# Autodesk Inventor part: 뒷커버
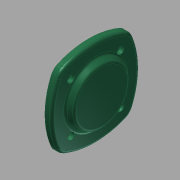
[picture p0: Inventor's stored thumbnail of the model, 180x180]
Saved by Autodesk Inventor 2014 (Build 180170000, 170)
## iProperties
Created: 2015-11
Part Number: 뒷커버
Material: 일반
Document SubType Name: Modeling
Designer: mduedu
Density: 1 g/cm^3
Appearance: 매끄러움 - 짙은 바다 녹색
Mass: 120.056 g
Surface Area: 247.583 cm^2
Volume: 120.056 cm^3
Author: mduedu
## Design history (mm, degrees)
sketch "스케치1"
  geometry: L1 (50, 50)-(-50, 50); L2 (-50, 50)-(-50, -50); L3 (-50, -50)-(50, -50); L4 (50, -50)-(50, 50); L5 (0, 50)-(0, -50); L6 (50, 0)-(-50, 0); A1 r 90 centre (-40, 0) between (40.415, -40.415) and (40.415, 40.415); A2 r 90 centre (40, 0) between (-40.415, 40.415) and (-40.415, -40.415); A3 r 90 centre (0, -40) between (40.415, 40.415) and (-40.415, 40.415); A4 r 90 centre (0, 40) between (-40.415, -40.415) and (40.415, -40.415); 2 further points
  constraints: 12 end point, 8 point on circle, 5 midpoint, 4 centre point, 2 horizontal alignment, 2 parallel, 2 perpendicular, 2 symmetric about line, 2 tangent, 2 vertical alignment, 1 equal radius, 1 horizontal, 2 other
  dimensions: "d0" = 100 distance of L3.end L1.start; "d2" = 90 radius of A1
extrude "돌출1" new body sketch "스케치1" distance "d3" = 8; taper "d4" = 0 deg
sketch "스케치2"
  geometry: C1 r 35 at (0, 0); 1 further point
  constraints: 1 centre point, 1 coincident
  dimensions: "d5" = 70 diameter of C1
extrude "돌출2" join sketch "스케치2" distance "d6" = 7; taper "d7" = -30 deg
sketch "스케치3"
  geometry: L1 (0, 0)-(0, 40); L2 (0, 0)-(-28.284, 28.284); A1 r 40 centre (0, 0) between (0, 40) and (-28.284, 28.284); 2 further points
  constraints: 4 end point, 2 coincident, 2 point on circle, 1 centre point, 1 vertical
  dimensions: "d8" = 80 diameter of A1; "d9" = 45 deg angle of L1 L2
hole "구멍1" sketch "스케치3" at (-28.284, 28.284) diameter "d11" = 4.5; stored, may be unused: countersink angle "d15" = 90 deg, drill point angle "d17" = 118 deg; dims "d12" = 6, "d13" = 8, "d14" = 4.4, "d16" = 8
sketch "스케치4"
  geometry: C1 r 35 at (0, 0); 1 further point
  constraints: 1 centre point, 1 coincident
  dimensions: "d21" = 70 diameter of C1
extrude "돌출3" join sketch "스케치4" distance "d23" = 12; taper "d24" = 0 deg
hole "구멍2" diameter "d27" = 30; stored, may be unused: countersink angle "d31" = 90 deg, drill point angle "d33" = 0 deg; dims "d25" = 10, "d26" = 10, "d28" = 6, "d29" = 40, "d30" = 12, "d32" = 15
fillet "모깎기2" dims "d35" = 15
fillet "모깎기3" dims "d36" = 3
fillet "모깎기4" dims "d37" = 3
fillet "모깎기5" dims "d38" = 0.3
chamfer "모따기1" distance "d39" = 1; stored, may be unused: second distance "d40" = 2, angle "d41" = 45 deg
node "솔리드1"
pattern_circular "원형 패턴1" dims angle "d19" = 360 deg
